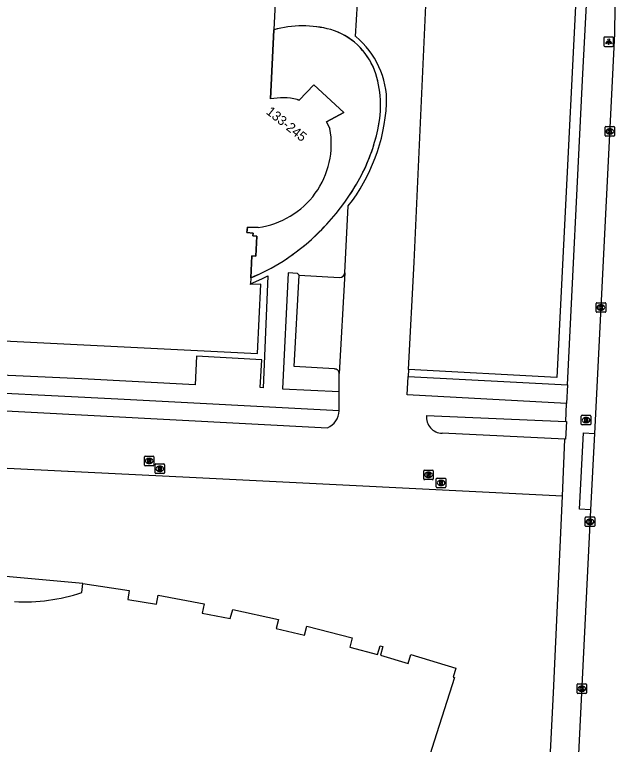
# Model space of a CAD drawing. Extents: x 161761 to 162722, y 384793 to 385405.
# Drawn here: x 162064.1 to 162127.2, y 385249.7 to 385326.1 of the extents above; entities that cross this region are included whole.
import ezdxf

# ---------------------------------------------------------------- set-up
doc = ezdxf.new("R2010")
doc.units = 0
for name, color, linetype in [('IMGEO_Brandkraan', 7, 'Continuous'), ('IMGEO_Groenvoorziening', 7, 'Continuous'), ('IMGEO_Haag', 7, 'Continuous'), ('IMGEO_Kolk', 7, 'Continuous'), ('IMGEO_Lichtpunt', 7, 'Continuous'), ('IMGEO_Pand', 7, 'Continuous'), ('IMGEO_Pand_nummerreeks', 7, 'Continuous'), ('IMGEO_Pand_overbouw', 7, 'Continuous'), ('IMGEO_Rijbaan_lokaal_gesloten', 7, 'Continuous'), ('IMGEO_Rijbaan_lokaal_open', 7, 'Continuous'), ('IMGEO_Rioolput', 7, 'Continuous'), ('IMGEO_Voetpad_open', 7, 'Continuous')]:
    doc.layers.add(name, color=color, linetype=linetype)

msp = doc.modelspace()

# ---------------------------------------------------------------- linework, layer by layer
at = {"layer": 'IMGEO_Brandkraan'}
for p, q in [((162123.505, 385283.226), (162123.505, 385284.078)), ((162123.58, 385284.152), (162124.432, 385284.152)), ((162123.993, 385283.932), (162124.018, 385283.932)), ((162124.506, 385284.078), (162124.506, 385283.226)), ((162124.432, 385283.152), (162123.58, 385283.152)), ((162124.016, 385283.372), (162123.991, 385283.372))]:
    msp.add_line(p, q, dxfattribs=at)
for points in [[(162123.505, 385283.226), (162123.505, 385284.078)], [(162123.58, 385284.152), (162124.432, 385284.152)], [(162124.506, 385284.078), (162124.506, 385283.226)], [(162124.432, 385283.152), (162123.58, 385283.152)], [(162123.853, 385283.852), (162123.853, 385283.452), (162124.066, 385283.452)], [(162124.084, 385283.852), (162123.853, 385283.852)], [(162124.032, 385283.771), (162123.978, 385283.771), (162123.978, 385283.695)], [(162123.978, 385283.695), (162124.031, 385283.695)], [(162124.04, 385283.619), (162123.978, 385283.619), (162123.978, 385283.538)], [(162123.978, 385283.538), (162124.04, 385283.538)]]:
    msp.add_lwpolyline(points, dxfattribs=at)
for centre, radius, start, end in [((162123.582, 385284.076), 0.0765, 91.55205, 178.44795), ((162123.582, 385284.076), 0.0765, 91.55205, 178.44795), ((162124.43, 385284.076), 0.0765, 1.55205, 88.44795), ((162124.43, 385284.076), 0.0765, 1.55205, 88.44795), ((162123.582, 385283.228), 0.0765, 181.55205, 268.44795), ((162123.582, 385283.228), 0.0765, 181.55205, 268.44795), ((162124.033, 385283.733), 0.0379, 267.82845, 90.93552), ((162124.041, 385283.578), 0.0404, 269.87594, 90.50774), ((162124.072, 385283.703), 0.251, 268.66757, 293.53466), ((162124.088, 385283.707), 0.145, 59.4692, 91.53667), ((162124.113, 385283.754), 0.0922, 285.51372, 58.15012), ((162124.118, 385283.562), 0.105, 301.31148, 78.98903), ((162124.43, 385283.228), 0.0765, 271.55205, 358.44795), ((162124.43, 385283.228), 0.0765, 271.55205, 358.44795)]:
    msp.add_arc(centre, radius, start, end, dxfattribs=at)
for centre, major_axis, ratio, start_param, end_param in [((162123.992, 385283.652), (-0.387, 0.002), 0.722429, 4.712389, 7.853982), ((162124.017, 385283.652), (-0.39, 0.002), 0.717154, 1.570796, 4.712389)]:
    msp.add_ellipse(centre, major_axis=major_axis, ratio=ratio, start_param=start_param, end_param=end_param, dxfattribs=at)
at = {"layer": 'IMGEO_Groenvoorziening'}
msp.add_lwpolyline([(162097.627, 385289.009), (162093.402, 385289.271), (162093.924, 385298.849)], dxfattribs=at)
msp.add_arc((162097.639, 385288.524), 0.485, 359.86402, 91.41823, dxfattribs=at)
at = {"layer": 'IMGEO_Haag'}
for points in [[(162124.058, 385351.671), (162123.76, 385344.448), (162120.957, 385288.114), (162105.398, 385288.95)], [(162105.36, 385288.235), (162122.052, 385287.335)]]:
    msp.add_lwpolyline(points, dxfattribs=at)
at = {"layer": 'IMGEO_Kolk'}
for p, q in [((162125.999, 385313.483), (162125.999, 385314.335)), ((162126.074, 385314.409), (162126.926, 385314.409)), ((162126.487, 385314.189), (162126.512, 385314.189)), ((162127, 385314.335), (162127, 385313.483)), ((162126.926, 385313.409), (162126.074, 385313.409)), ((162126.51, 385313.629), (162126.485, 385313.629)), ((162125.063, 385295.025), (162125.063, 385295.877)), ((162125.138, 385295.951), (162125.99, 385295.951)), ((162125.551, 385295.731), (162125.576, 385295.731)), ((162126.064, 385295.877), (162126.064, 385295.025)), ((162125.99, 385294.951), (162125.138, 385294.951)), ((162125.574, 385295.171), (162125.549, 385295.171)), ((162123.917, 385272.568), (162123.917, 385273.42)), ((162123.992, 385273.494), (162124.844, 385273.494)), ((162124.405, 385273.274), (162124.43, 385273.274)), ((162124.918, 385273.42), (162124.918, 385272.568)), ((162124.844, 385272.494), (162123.992, 385272.494)), ((162124.428, 385272.714), (162124.403, 385272.714)), ((162123.056, 385255.069), (162123.056, 385255.921)), ((162123.131, 385255.995), (162123.983, 385255.995)), ((162123.544, 385255.775), (162123.569, 385255.775)), ((162124.057, 385255.921), (162124.057, 385255.069)), ((162123.983, 385254.995), (162123.131, 385254.995)), ((162123.567, 385255.215), (162123.542, 385255.215))]:
    msp.add_line(p, q, dxfattribs=at)
for points in [[(162125.999, 385313.483), (162125.999, 385314.335)], [(162126.074, 385314.409), (162126.926, 385314.409)], [(162126.32, 385314.109), (162126.443, 385314.109), (162126.443, 385313.958), (162126.573, 385314.109), (162126.737, 385314.109), (162126.591, 385313.958), (162126.744, 385313.709), (162126.592, 385313.709), (162126.507, 385313.873), (162126.443, 385313.806), (162126.443, 385313.709), (162126.32, 385313.709), (162126.32, 385314.109)], [(162127, 385314.335), (162127, 385313.483)], [(162126.926, 385313.409), (162126.074, 385313.409)], [(162125.063, 385295.025), (162125.063, 385295.877)], [(162125.138, 385295.951), (162125.99, 385295.951)], [(162125.384, 385295.651), (162125.507, 385295.651), (162125.507, 385295.5), (162125.637, 385295.651), (162125.801, 385295.651), (162125.655, 385295.5), (162125.808, 385295.251), (162125.656, 385295.251), (162125.571, 385295.415), (162125.507, 385295.348), (162125.507, 385295.251), (162125.384, 385295.251), (162125.384, 385295.651)], [(162126.064, 385295.877), (162126.064, 385295.025)], [(162125.99, 385294.951), (162125.138, 385294.951)], [(162123.917, 385272.568), (162123.917, 385273.42)], [(162123.992, 385273.494), (162124.844, 385273.494)], [(162124.238, 385273.194), (162124.361, 385273.194), (162124.361, 385273.043), (162124.491, 385273.194), (162124.655, 385273.194), (162124.509, 385273.043), (162124.662, 385272.794), (162124.51, 385272.794), (162124.425, 385272.958), (162124.361, 385272.891), (162124.361, 385272.794), (162124.238, 385272.794), (162124.238, 385273.194)], [(162124.918, 385273.42), (162124.918, 385272.568)], [(162124.844, 385272.494), (162123.992, 385272.494)], [(162123.056, 385255.069), (162123.056, 385255.921)], [(162123.131, 385255.995), (162123.983, 385255.995)], [(162123.377, 385255.695), (162123.5, 385255.695), (162123.5, 385255.544), (162123.63, 385255.695), (162123.794, 385255.695), (162123.648, 385255.544), (162123.801, 385255.295), (162123.649, 385255.295), (162123.564, 385255.459), (162123.5, 385255.392), (162123.5, 385255.295), (162123.377, 385255.295), (162123.377, 385255.695)], [(162124.057, 385255.921), (162124.057, 385255.069)], [(162123.983, 385254.995), (162123.131, 385254.995)]]:
    msp.add_lwpolyline(points, dxfattribs=at)
for centre, start, end in [((162126.076, 385314.333), 91.55205, 178.44795), ((162126.076, 385314.333), 91.55205, 178.44795), ((162126.924, 385314.333), 1.55205, 88.44795), ((162126.924, 385314.333), 1.55205, 88.44795), ((162126.076, 385313.485), 181.55205, 268.44795), ((162126.076, 385313.485), 181.55205, 268.44795), ((162126.924, 385313.485), 271.55205, 358.44795), ((162126.924, 385313.485), 271.55205, 358.44795), ((162125.14, 385295.875), 91.55205, 178.44795), ((162125.14, 385295.875), 91.55205, 178.44795), ((162125.988, 385295.875), 1.55205, 88.44795), ((162125.988, 385295.875), 1.55205, 88.44795), ((162125.14, 385295.027), 181.55205, 268.44795), ((162125.14, 385295.027), 181.55205, 268.44795), ((162125.988, 385295.027), 271.55205, 358.44795), ((162125.988, 385295.027), 271.55205, 358.44795), ((162123.994, 385273.418), 91.55205, 178.44795), ((162123.994, 385273.418), 91.55205, 178.44795), ((162124.842, 385273.418), 1.55205, 88.44795), ((162124.842, 385273.418), 1.55205, 88.44795), ((162123.994, 385272.57), 181.55205, 268.44795), ((162123.994, 385272.57), 181.55205, 268.44795), ((162124.842, 385272.57), 271.55205, 358.44795), ((162124.842, 385272.57), 271.55205, 358.44795), ((162123.133, 385255.919), 91.55205, 178.44795), ((162123.133, 385255.919), 91.55205, 178.44795), ((162123.981, 385255.919), 1.55205, 88.44795), ((162123.981, 385255.919), 1.55205, 88.44795), ((162123.133, 385255.071), 181.55205, 268.44795), ((162123.133, 385255.071), 181.55205, 268.44795), ((162123.981, 385255.071), 271.55205, 358.44795), ((162123.981, 385255.071), 271.55205, 358.44795)]:
    msp.add_arc(centre, 0.0765, start, end, dxfattribs=at)
for centre, major_axis, ratio, start_param, end_param in [((162126.486, 385313.909), (-0.387, 0.002), 0.722429, 4.712389, 7.853982), ((162126.511, 385313.909), (-0.39, 0.002), 0.717154, 1.570796, 4.712389), ((162125.55, 385295.451), (-0.387, 0.002), 0.722429, 4.712389, 7.853982), ((162125.575, 385295.451), (-0.39, 0.002), 0.717154, 1.570796, 4.712389), ((162124.404, 385272.994), (-0.387, 0.002), 0.722429, 4.712389, 7.853982), ((162124.429, 385272.994), (-0.39, 0.002), 0.717154, 1.570796, 4.712389), ((162123.543, 385255.495), (-0.387, 0.002), 0.722429, 4.712389, 7.853982), ((162123.568, 385255.495), (-0.39, 0.002), 0.717154, 1.570796, 4.712389)]:
    msp.add_ellipse(centre, major_axis=major_axis, ratio=ratio, start_param=start_param, end_param=end_param, dxfattribs=at)
at = {"layer": 'IMGEO_Lichtpunt'}
for p, q in [((162125.878, 385323.704), (162125.878, 385322.897)), ((162125.878, 385323.704), (162125.878, 385322.897)), ((162126.78, 385323.799), (162125.972, 385323.799)), ((162126.78, 385323.799), (162125.972, 385323.799)), ((162126.874, 385322.897), (162126.874, 385323.704)), ((162126.874, 385322.897), (162126.874, 385323.704)), ((162125.972, 385322.803), (162126.78, 385322.803)), ((162125.972, 385322.803), (162126.78, 385322.803))]:
    msp.add_line(p, q, dxfattribs=at)
for points in [[(162126.252, 385323.368), (162126.291, 385323.34), (162126.103, 385323.078), (162126.065, 385323.105), (162126.252, 385323.368)], [(162126.354, 385323.32), (162126.401, 385323.32), (162126.401, 385322.998), (162126.354, 385322.998), (162126.354, 385323.32)], [(162126.464, 385323.34), (162126.502, 385323.367), (162126.689, 385323.105), (162126.65, 385323.077), (162126.464, 385323.34)]]:
    msp.add_lwpolyline(points, dxfattribs=at)
msp.add_circle((162126.377, 385323.502), 0.0994, dxfattribs=at)
for centre, start, end in [((162125.972, 385323.704), 90, 180), ((162125.972, 385323.704), 90, 180), ((162126.78, 385323.704), 0, 90), ((162126.78, 385323.704), 0, 90), ((162125.972, 385322.897), 180, 270), ((162125.972, 385322.897), 180, 270), ((162126.78, 385322.897), 270, 0), ((162126.78, 385322.897), 270, 360)]:
    msp.add_arc(centre, 0.0946, start, end, dxfattribs=at)
at = {"layer": 'IMGEO_Pand'}
for points in [[(162069.876, 385342.73), (162076.599, 385342.392), (162092.129, 385341.645), (162091.282, 385324.562)], [(162090.923, 385317.316), (162091.282, 385324.562)], [(162097.15, 385314.213), (162096.803, 385314.905), (162098.608, 385315.88), (162095.457, 385318.788), (162093.944, 385317.186), (162093.708, 385317.259)], [(162088.856, 385298.567), (162088.976, 385300.882), (162089.397, 385300.836), (162089.498, 385302.937), (162089.079, 385302.969), (162089.102, 385303.241), (162088.454, 385303.297), (162088.504, 385303.874), (162089.645, 385303.85)], [(162088.856, 385298.567), (162088.823, 385297.914)], [(162056.667, 385292.277), (162089.575, 385290.639), (162089.919, 385297.91), (162088.821, 385297.876), (162088.823, 385297.914)], [(162071.146, 385265.564), (162071.273, 385266.531), (162076.122, 385265.779), (162075.975, 385264.83), (162078.964, 385264.349), (162079.141, 385265.302), (162083.968, 385264.388), (162083.766, 385263.411), (162086.713, 385262.865), (162086.964, 385263.809), (162091.753, 385262.745), (162091.536, 385261.803), (162094.481, 385261.117), (162094.73, 385262.055), (162099.483, 385260.814), (162099.251, 385259.842), (162102.158, 385259.094), (162102.428, 385260.004), (162102.719, 385259.92), (162102.453, 385259), (162105.369, 385258.134), (162105.652, 385259.076), (162110.348, 385257.65), (162110.064, 385256.713), (162110.226, 385256.657), (162108.097, 385250), (162105.873, 385243.044)]]:
    msp.add_lwpolyline(points, dxfattribs=at)
for centre, radius, start, end in [((162092.174, 385310.356), 7.071, 77.46799, 100.18702), ((162088.482, 385312.592), 8.819, 277.58057, 10.59448), ((162065.136, 385283.844), 19.243, 266.93392, 288.19884)]:
    msp.add_arc(centre, radius, start, end, dxfattribs=at)
at = {"layer": 'IMGEO_Pand_overbouw'}
for points in [[(162089.645, 385303.85), (162088.504, 385303.874), (162088.454, 385303.297), (162089.102, 385303.241), (162089.079, 385302.969), (162089.498, 385302.937), (162089.397, 385300.836), (162088.976, 385300.882), (162088.856, 385298.567), (162089.296, 385298.751), (162089.731, 385298.945), (162090.162, 385299.15), (162090.588, 385299.364), (162091.01, 385299.587), (162091.426, 385299.82), (162091.836, 385300.063), (162092.241, 385300.314), (162092.863, 385300.731), (162093.473, 385301.168), (162094.07, 385301.624), (162094.652, 385302.099), (162095.218, 385302.593), (162095.769, 385303.103), (162096.302, 385303.631), (162096.818, 385304.174), (162097.317, 385304.73), (162097.799, 385305.302), (162098.264, 385305.888), (162098.711, 385306.489), (162099.14, 385307.104), (162099.549, 385307.731), (162099.938, 385308.369), (162100.308, 385309.019), (162100.617, 385309.62), (162100.906, 385310.232), (162101.173, 385310.855), (162101.42, 385311.487), (162101.644, 385312.127), (162101.846, 385312.774), (162102.026, 385313.427), (162102.183, 385314.085), (162102.264, 385314.468), (162102.331, 385314.855), (162102.386, 385315.245), (162102.427, 385315.639), (162102.453, 385316.034), (162102.466, 385316.431), (162102.465, 385316.829), (162102.45, 385317.227), (162102.421, 385317.624), (162102.377, 385318.019), (162102.32, 385318.412), (162102.249, 385318.803), (162102.165, 385319.189), (162102.067, 385319.571), (162101.956, 385319.948), (162101.833, 385320.319), (162101.682, 385320.682), (162101.508, 385321.04), (162101.313, 385321.391), (162101.096, 385321.733), (162100.859, 385322.065), (162100.602, 385322.384), (162100.326, 385322.688), (162100.032, 385322.977), (162099.722, 385323.248), (162099.398, 385323.5), (162099.06, 385323.733), (162098.712, 385323.944), (162098.355, 385324.135), (162097.99, 385324.303), (162097.62, 385324.449), (162097.247, 385324.573), (162096.884, 385324.664), (162096.518, 385324.744), (162096.148, 385324.812), (162095.775, 385324.867), (162095.399, 385324.911), (162095.022, 385324.941), (162094.643, 385324.96), (162094.264, 385324.965), (162093.884, 385324.958), (162093.506, 385324.938), (162093.128, 385324.906), (162092.753, 385324.862), (162092.38, 385324.805), (162092.01, 385324.735), (162091.644, 385324.654), (162091.282, 385324.562)], [(162091.282, 385324.562), (162090.923, 385317.316)], [(162093.708, 385317.259), (162093.944, 385317.186), (162095.457, 385318.788), (162098.608, 385315.88), (162096.803, 385314.905), (162097.15, 385314.213)], [(162071.146, 385265.564), (162071.273, 385266.531), (162055.497, 385267.968), (162056.667, 385292.277)]]:
    msp.add_lwpolyline(points, dxfattribs=at)
for centre, radius, start, end in [((162092.174, 385310.356), 7.071, 77.46799, 100.18702), ((162088.482, 385312.592), 8.819, 277.58057, 10.59448), ((162065.136, 385283.844), 19.243, 266.93392, 288.19884)]:
    msp.add_arc(centre, radius, start, end, dxfattribs=at)
at = {"layer": 'IMGEO_Rijbaan_lokaal_gesloten'}
for points in [[(162127.185, 385353.161), (162127.085, 385332.496), (162126.992, 385324.158), (162126.732, 385319.163), (162124.878, 385282.238)], [(162124.878, 385282.238), (162124.469, 385274.256)], [(162124.469, 385274.256), (162122.219, 385228.776)]]:
    msp.add_lwpolyline(points, dxfattribs=at)
at = {"layer": 'IMGEO_Rijbaan_lokaal_open'}
for points in [[(162105.398, 385288.95), (162106.002, 385300.194), (162108.333, 385351.725)], [(162099.856, 385323.836), (162100.041, 385327.331)], [(162098.709, 385299.073), (162099.078, 385306.092)], [(162098.709, 385299.073), (162098.124, 385288.523)], [(162098.133, 385286.639), (162098.124, 385288.523)], [(162105.398, 385288.95), (162105.36, 385288.235)], [(162121.956, 385285.388), (162105.255, 385286.288), (162105.36, 385288.235)], [(162098.143, 385284.617), (162098.133, 385286.639)], [(162055.318, 385285.029), (162056.316, 385284.979), (162056.544, 385284.967), (162096.901, 385282.85)], [(162121.873, 385283.503), (162121.956, 385285.388)], [(162107.279, 385284.136), (162121.873, 385283.503)], [(162121.795, 385281.655), (162108.914, 385282.264)], [(162121.521, 385275.665), (162121.795, 385281.655)], [(162121.521, 385275.665), (162083.133, 385277.615), (162056.237, 385278.926), (162055.602, 385278.957), (162053.548, 385279.049), (162050.835, 385279.171)]]:
    msp.add_lwpolyline(points, dxfattribs=at)
for centre, radius, start, end in [((162094.307, 385317.007), 8.799, 358.52687, 50.90077), ((162083.804, 385317.946), 19.335, 322.18614, 356.54559), ((162096.073, 385284.752), 2.075, 293.52768, 356.26661), ((162108.974, 385283.967), 1.704, 174.29511, 267.97265)]:
    msp.add_arc(centre, radius, start, end, dxfattribs=at)
at = {"layer": 'IMGEO_Rioolput'}
for p, q in [((162077.713, 385278.943), (162077.713, 385279.795)), ((162077.788, 385279.869), (162078.64, 385279.869)), ((162078.201, 385279.649), (162078.226, 385279.649)), ((162078.714, 385279.795), (162078.714, 385278.943)), ((162078.64, 385278.869), (162077.788, 385278.869)), ((162078.224, 385279.089), (162078.199, 385279.089)), ((162078.826, 385278.123), (162078.826, 385278.975)), ((162078.901, 385279.049), (162079.753, 385279.049)), ((162079.314, 385278.829), (162079.339, 385278.829)), ((162079.827, 385278.975), (162079.827, 385278.123)), ((162079.753, 385278.049), (162078.901, 385278.049)), ((162079.337, 385278.269), (162079.312, 385278.269)), ((162106.99, 385277.48), (162106.99, 385278.332)), ((162107.065, 385278.406), (162107.917, 385278.406)), ((162107.478, 385278.186), (162107.503, 385278.186)), ((162107.991, 385278.332), (162107.991, 385277.48)), ((162107.917, 385277.406), (162107.065, 385277.406)), ((162107.501, 385277.626), (162107.476, 385277.626)), ((162108.308, 385276.638), (162108.308, 385277.49)), ((162108.383, 385277.564), (162109.235, 385277.564)), ((162108.796, 385277.344), (162108.821, 385277.344)), ((162109.309, 385277.49), (162109.309, 385276.638)), ((162109.235, 385276.564), (162108.383, 385276.564)), ((162108.819, 385276.784), (162108.794, 385276.784))]:
    msp.add_line(p, q, dxfattribs=at)
for points in [[(162077.713, 385278.943), (162077.713, 385279.795)], [(162077.788, 385279.869), (162078.64, 385279.869)], [(162078.302, 385279.567), (162078.05, 385279.569), (162078.05, 385279.169)], [(162078.05, 385279.169), (162078.174, 385279.169), (162078.174, 385279.331), (162078.185, 385279.331)], [(162078.228, 385279.488), (162078.174, 385279.488), (162078.174, 385279.407)], [(162078.174, 385279.407), (162078.226, 385279.407)], [(162078.232, 385279.302), (162078.303, 385279.169), (162078.443, 385279.169), (162078.378, 385279.295)], [(162078.714, 385279.795), (162078.714, 385278.943)], [(162078.64, 385278.869), (162077.788, 385278.869)], [(162078.826, 385278.123), (162078.826, 385278.975)], [(162078.901, 385279.049), (162079.753, 385279.049)], [(162079.415, 385278.747), (162079.163, 385278.749), (162079.163, 385278.349)], [(162079.341, 385278.668), (162079.287, 385278.668), (162079.287, 385278.587)], [(162079.287, 385278.587), (162079.339, 385278.587)], [(162079.827, 385278.975), (162079.827, 385278.123)], [(162079.753, 385278.049), (162078.901, 385278.049)], [(162079.163, 385278.349), (162079.287, 385278.349), (162079.287, 385278.511), (162079.298, 385278.511)], [(162079.345, 385278.482), (162079.416, 385278.349), (162079.556, 385278.349), (162079.491, 385278.475)], [(162106.99, 385277.48), (162106.99, 385278.332)], [(162107.065, 385278.406), (162107.917, 385278.406)], [(162107.579, 385278.104), (162107.327, 385278.106), (162107.327, 385277.706)], [(162107.327, 385277.706), (162107.451, 385277.706), (162107.451, 385277.868), (162107.462, 385277.868)], [(162107.505, 385278.025), (162107.451, 385278.025), (162107.451, 385277.944)], [(162107.451, 385277.944), (162107.503, 385277.944)], [(162107.509, 385277.839), (162107.58, 385277.706), (162107.72, 385277.706), (162107.655, 385277.832)], [(162107.991, 385278.332), (162107.991, 385277.48)], [(162107.917, 385277.406), (162107.065, 385277.406)], [(162108.308, 385276.638), (162108.308, 385277.49)], [(162108.383, 385277.564), (162109.235, 385277.564)], [(162108.897, 385277.262), (162108.645, 385277.264), (162108.645, 385276.864)], [(162108.645, 385276.864), (162108.769, 385276.864), (162108.769, 385277.026), (162108.78, 385277.026)], [(162108.823, 385277.183), (162108.769, 385277.183), (162108.769, 385277.102)], [(162108.769, 385277.102), (162108.821, 385277.102)], [(162108.827, 385276.997), (162108.898, 385276.864), (162109.038, 385276.864), (162108.973, 385276.99)], [(162109.309, 385277.49), (162109.309, 385276.638)], [(162109.235, 385276.564), (162108.383, 385276.564)]]:
    msp.add_lwpolyline(points, dxfattribs=at)
for centre, radius, start, end in [((162077.79, 385279.793), 0.0765, 91.55205, 178.44795), ((162077.79, 385279.793), 0.0765, 91.55205, 178.44795), ((162078.184, 385279.278), 0.0533, 26.02933, 88.69889), ((162078.21, 385279.596), 0.19, 274.7715, 282.96867), ((162078.234, 385279.392), 0.0964, 77.00612, 93.18647), ((162078.248, 385279.449), 0.0378, 276.66336, 79.67722), ((162078.301, 385279.457), 0.109, 350.36119, 89.41601), ((162078.299, 385279.457), 0.112, 277.58423, 350.98172), ((162078.283, 385279.242), 0.108, 29.51342, 73.79051), ((162078.638, 385279.793), 0.0765, 1.55205, 88.44795), ((162078.638, 385279.793), 0.0765, 1.55205, 88.44795), ((162077.79, 385278.945), 0.0765, 181.55205, 268.44795), ((162077.79, 385278.945), 0.0765, 181.55205, 268.44795), ((162078.638, 385278.945), 0.0765, 271.55205, 358.44795), ((162078.638, 385278.945), 0.0765, 271.55205, 358.44795), ((162078.903, 385278.973), 0.0765, 91.55205, 178.44795), ((162078.903, 385278.973), 0.0765, 91.55205, 178.44795), ((162079.323, 385278.776), 0.19, 274.7715, 282.96867), ((162079.347, 385278.572), 0.0964, 77.00612, 93.18647), ((162079.361, 385278.629), 0.0378, 276.66336, 79.67722), ((162079.414, 385278.637), 0.109, 350.36119, 89.41601), ((162079.412, 385278.637), 0.112, 277.58423, 350.98172), ((162079.396, 385278.422), 0.108, 29.51342, 73.79051), ((162079.751, 385278.973), 0.0765, 1.55205, 88.44795), ((162079.751, 385278.973), 0.0765, 1.55205, 88.44795), ((162078.903, 385278.125), 0.0765, 181.55205, 268.44795), ((162078.903, 385278.125), 0.0765, 181.55205, 268.44795), ((162079.297, 385278.458), 0.0533, 26.02933, 88.69889), ((162079.751, 385278.125), 0.0765, 271.55205, 358.44795), ((162079.751, 385278.125), 0.0765, 271.55205, 358.44795), ((162107.067, 385278.33), 0.0765, 91.55205, 178.44795), ((162107.067, 385278.33), 0.0765, 91.55205, 178.44795), ((162107.461, 385277.815), 0.0533, 26.02933, 88.69889), ((162107.487, 385278.133), 0.19, 274.7715, 282.96867), ((162107.511, 385277.929), 0.0964, 77.00612, 93.18647), ((162107.525, 385277.986), 0.0378, 276.66336, 79.67722), ((162107.578, 385277.994), 0.109, 350.36119, 89.41601), ((162107.576, 385277.994), 0.112, 277.58423, 350.98172), ((162107.56, 385277.779), 0.108, 29.51342, 73.79051), ((162107.915, 385278.33), 0.0765, 1.55205, 88.44795), ((162107.915, 385278.33), 0.0765, 1.55205, 88.44795), ((162107.067, 385277.482), 0.0765, 181.55205, 268.44795), ((162107.067, 385277.482), 0.0765, 181.55205, 268.44795), ((162107.915, 385277.482), 0.0765, 271.55205, 358.44795), ((162107.915, 385277.482), 0.0765, 271.55205, 358.44795), ((162108.385, 385277.488), 0.0765, 91.55205, 178.44795), ((162108.385, 385277.488), 0.0765, 91.55205, 178.44795), ((162108.779, 385276.973), 0.0533, 26.02933, 88.69889), ((162108.805, 385277.291), 0.19, 274.7715, 282.96867), ((162108.829, 385277.087), 0.0964, 77.00612, 93.18647), ((162108.843, 385277.144), 0.0378, 276.66336, 79.67722), ((162108.896, 385277.152), 0.109, 350.36119, 89.41601), ((162108.894, 385277.152), 0.112, 277.58423, 350.98172), ((162108.878, 385276.937), 0.108, 29.51342, 73.79051), ((162109.233, 385277.488), 0.0765, 1.55205, 88.44795), ((162109.233, 385277.488), 0.0765, 1.55205, 88.44795), ((162108.385, 385276.64), 0.0765, 181.55205, 268.44795), ((162108.385, 385276.64), 0.0765, 181.55205, 268.44795), ((162109.233, 385276.64), 0.0765, 271.55205, 358.44795), ((162109.233, 385276.64), 0.0765, 271.55205, 358.44795)]:
    msp.add_arc(centre, radius, start, end, dxfattribs=at)
for centre, major_axis, ratio, start_param, end_param in [((162078.2, 385279.369), (-0.387, 0.002), 0.722429, 4.712389, 7.853982), ((162078.225, 385279.369), (-0.39, 0.002), 0.717154, 1.570796, 4.712389), ((162079.313, 385278.549), (-0.387, 0.002), 0.722429, 4.712389, 7.853982), ((162079.338, 385278.549), (-0.39, 0.002), 0.717154, 1.570796, 4.712389), ((162107.477, 385277.906), (-0.387, 0.002), 0.722429, 4.712389, 7.853982), ((162107.502, 385277.906), (-0.39, 0.002), 0.717154, 1.570796, 4.712389), ((162108.795, 385277.064), (-0.387, 0.002), 0.722429, 4.712389, 7.853982), ((162108.82, 385277.064), (-0.39, 0.002), 0.717154, 1.570796, 4.712389)]:
    msp.add_ellipse(centre, major_axis=major_axis, ratio=ratio, start_param=start_param, end_param=end_param, dxfattribs=at)
at = {"layer": 'IMGEO_Voetpad_open'}
for points in [[(162122.052, 385287.335), (162123.635, 385319.287), (162124.144, 385329.185), (162124.937, 385344.85), (162125.282, 385351.667)], [(162088.823, 385297.914), (162090.024, 385298.468), (162090.663, 385298.763), (162090.553, 385296.234), (162090.151, 385287.029), (162089.851, 385287.051), (162090.009, 385289.962), (162083.181, 385290.342), (162083.046, 385287.356), (162071.152, 385287.989), (162056.492, 385288.65)], [(162093.924, 385298.849), (162093.769, 385299.017), (162092.793, 385299.072), (162092.186, 385286.922), (162098.133, 385286.639)], [(162093.924, 385298.849), (162098.178, 385298.601)], [(162122.052, 385287.335), (162121.956, 385285.388)], [(162098.143, 385284.617), (162074.929, 385285.836), (162055.428, 385286.819)], [(162121.873, 385283.503), (162121.967, 385283.492), (162121.859, 385281.652), (162121.795, 385281.655)], [(162124.469, 385274.256), (162123.313, 385274.317), (162123.721, 385282.3), (162124.878, 385282.238)], [(162119.21, 385227.479), (162120.58, 385255.067), (162121.521, 385275.665)]]:
    msp.add_lwpolyline(points, dxfattribs=at)
for centre, radius, start, end in [((162094.285, 385313.577), 11.388, 74.92268, 105.28864), ((162095.191, 385317.758), 7.118, 21.08722, 73.21442), ((162091.239, 385316.597), 11.229, 347.07124, 19.35561), ((162082.963, 385318.319), 19.681, 331.80184, 347.57767), ((162078.804, 385320.829), 24.534, 317.24393, 331.22338), ((162079.371, 385320.218), 23.702, 302.88638, 317.39865), ((162080.906, 385318.123), 21.11, 292.12183, 302.47473), ((162098.207, 385299.103), 0.503, 266.67466, 356.59242)]:
    msp.add_arc(centre, radius, start, end, dxfattribs=at)

# ---------------------------------------------------------------- texts
at = {"layer": 'IMGEO_Pand_nummerreeks'}
msp.add_text('133-245', height=1, rotation=321.41702, dxfattribs=at).set_placement((162090.391, 385315.825))

doc.saveas('drawing.dxf')
